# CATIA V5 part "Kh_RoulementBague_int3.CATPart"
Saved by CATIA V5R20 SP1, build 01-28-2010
Part number: Roulement bague int 3
Bounding box of the stored display mesh (mm): x -12.495 to 12.495, y -12.495 to 12.495, z -10 to 2
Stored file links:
  G:\Khaled_CFAO_2011\SIL\SIL_GR1\tmerino\Khaled\CAD_Thinkmotion\Kh_RoulementBague_int3.CATPart
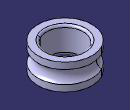
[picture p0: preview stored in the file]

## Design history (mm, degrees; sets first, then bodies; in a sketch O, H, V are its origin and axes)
Body1 (main body)
  Sketch1 on yz-plane, origin (0, 0, 0), H (0, 1, 0), V (0, 0, 1)
    line L1 (8.5, -10) -> (8.5, 2)
    line L2 (8.5, 2) -> (12.5, 2)
    line L3 (8.5, -10) -> (12.5, -10)
    line L4 (12.5, 2) -> (12.5, -1)
    line L5 (12.5, -10) -> (12.5, -7)
    arc A1 centre (14.25, -4) radius 3.4731 from (12.5, -1) to (12.5, -7) ccw
    distance L1 V = 8.5
    length L2 = 4
    length L3 = 4
    length L1 = 12
    length L4 = 3
    length L5 = 3
    vertical: L1 V, L4 V, L5 V
    horizontal: L2 H, L3 H
  Shaft1: profile Sketch1, axis Sketch1.V, angle 360
  Fillet1: radius 1, on face of Shaft1 from Sketch1.L1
